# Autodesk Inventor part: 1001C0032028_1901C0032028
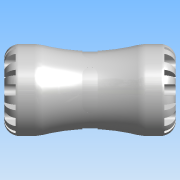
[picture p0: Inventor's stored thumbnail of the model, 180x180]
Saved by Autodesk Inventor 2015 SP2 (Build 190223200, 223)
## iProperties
Created: 2016-12
Part Number: 1001C0032028_1901C0032028
Material: PVC-Piping
Description: PLASSON COPPER PIPE ADAPTOR 32X28 SERIES 1
Document SubType Name: Modeling
Designer: KIM
Mass: 95.2094 g
Surface Area: 200.83 cm^2
Volume: 68.0067 cm^3
Density: 1.4 g/cm^3
Appearance: Smooth - White
ILogicFactory: False
Author: KIM
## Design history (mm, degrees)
derived "1001C.ipt"
feature "Solid1::1001C.ipt"
tag "TaggingFeature1"
body "Solid1"
other parameters: "d1" = 58, "d2" = 53, "d11" = 7.2, "d13" = 7.2, "d14" = 0, "d16" = 360 deg, "d18" = 8 deg, "d19" = 0.64, "d20" = 8 deg, "d21" = 0.64, "d23" = 0, "d25" = 360 deg, "d27" = 23.2, "d28" = 9.6, "d29" = 9.6, "d30" = 14.112, "d31" = 0, "d33" = 0, "d37" = 21.6, "d38" = 0.58, "d44" = 32, "d45" = 21.6, "d46" = 49.3, "d47" = 58, "d50" = 360 deg, "d54" = 0.513, "d60" = 28, "d62" = 58, "d63" = 21.6, "d64" = 108, "d65" = 53, "d66" = 2.33333, "d67" = 54, "d70" = 7.2, "d72" = 7.2, "d73" = 0, "d75" = 360 deg, "d77" = 8 deg, "d78" = 8 deg, "d79" = 0.64, "d80" = 0.64, "d82" = 0, "d84" = 360 deg, "d_" = 32, "E_" = 58, "H_" = 108, "l_" = 53, "d_1" = 28, "E_1" = 58, "l_1" = 53, "d42" = 58, "d52" = 9, "d68" = 58, "d71" = 9
